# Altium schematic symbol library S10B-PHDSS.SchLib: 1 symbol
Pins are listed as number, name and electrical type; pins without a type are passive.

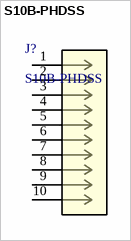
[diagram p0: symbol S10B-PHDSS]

## S10B-PHDSS
designator J?
Description; Manufacturer_Name: JST
footprint CONN10_S10B_JST
pins: 1, 2, 3, 4, 5, 6, 7, 8, 9, 10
